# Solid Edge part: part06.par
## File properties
Author: Robert a Rhodes jr
Template: normal.par
Last saved by: Rajat Kamboj
Revision: 13
Application: Solid Edge
Accuracy: 0.99
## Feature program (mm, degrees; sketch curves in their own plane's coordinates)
sketch for "unnamed Protrusion 1" plane through (0, 0, 0) normal (0, -1, 0) x-axis (1, 0, 0)
  arc centre (60, 0) radius 30 from (60, 30) to (60, -30) cw
  line (104, -30) -> (60, -30)
  line (104, 18) -> (104, -30)
  line (164, 18) -> (104, 18)
  line (164, -4) -> (164, 18)
  line (182, -4) -> (164, -4)
  line (182, -4) -> (182, 36)
  line (142, 36) -> (182, 36)
  line (142, 30) -> (142, 36)
  line (60, 30) -> (142, 30)
extrude "unnamed Protrusion 1" add finite 54 symmetric
sketch for "ExtrudedProtrusion_6" #1 plane through (0, 0, 0) normal (0, -1, 0) x-axis (1, 0, 0)
  arc centre (60, 0) radius 30 from (60, 30) to (60, -30) ccw
  arc centre (60, 0) radius 30 from (60, 30) to (60, -30) cw
sketch for "ExtrudedProtrusion_6" #2 plane through (0, 0, 0) normal (0, -1, 0) x-axis (1, 0, 0)
  circle centre (60, 0) radius 18
extrude "ExtrudedProtrusion_6" add finite 66 symmetric
sketch for "ExtrudedProtrusion_7" plane through (0, 0, 0) normal (0, -1, 0) x-axis (1, 0, 0)
  line (104, -30) -> (164, -4)
  line (164, -4) -> (164, 18)
  line (164, 18) -> (104, 18)
  line (104, 18) -> (104, -30)
extrude "ExtrudedProtrusion_7" add finite 18 symmetric
sketch for "ExtrudedProtrusion_8" plane through (0, 0, 0) normal (0, -1, 0) x-axis (1, 0, 0)
  line (200, 76) -> (200, -4)
  line (200, -4) -> (182, -4)
  line (182, -4) -> (182, 36)
  line (182, 76) -> (182, 36)
  line (182, 76) -> (200, 76)
extrude "ExtrudedProtrusion_8" add finite 92 symmetric
sketch for "ExtrudedProtrusion_9" plane through (0, 0, 0) normal (0, -1, 0) x-axis (1, 0, 0)
  line (142, 36) -> (182, 76)
  line (182, 76) -> (182, 36)
  line (142, 36) -> (182, 36)
extrude "ExtrudedProtrusion_9" add finite 12 symmetric
sketch for "unnamed Hole 1" plane through (200, 0, 36) normal (1, 0, 0) x-axis (0, 1, 0)
hole "unnamed Hole 1" through
sketch for "Hole_1" plane through (200, 0, 36) normal (1, 0, 0) x-axis (0, 1, 0)
hole "Hole_1" diameter 16 through
pattern "unnamed Pattern 1" of "unnamed Hole 1", "Hole_1"
fillet "unnamed Round 1"
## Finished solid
Body 1: solid body, 34 faces, 81 edges, 46 vertices.
  Faces by surface: plane 28, cylinder 6
  Edges by curve: line 67, circle 14
Bounding box of the edges (mm): 170.000 x 92.000 x 106.000, from (30, -46, -30) to (200, 46, 76).
Cylindrical faces by radius (mm): R8 x2, R16 x2, R18 x1, R30 x1
Planar faces by outward normal: +x 3, +y 5, +z 4, -x 5, -y 5, -z 4, oblique 2
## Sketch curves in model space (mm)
circle centre (60, 0, 0) radius 18
line (182, 0, -4) -> (164, 0, -4)
line (104, 0, -30) -> (60, 0, -30)
arc centre (60, 0, 0) radius 30 from (60, 0, 30) through (30.0132, 0, -0.889) to (60, 0, -30)
arc centre (60, 0, 0) radius 30 from (60, 0, 30) through (89.9868, 0, -0.889) to (60, 0, -30)
line (142, 0, 36) -> (182, 0, 76)
line (142, 0, 36) -> (182, 0, 36)
line (104, 0, -30) -> (164, 0, -4)
line (182, 0, 76) -> (182, 0, 36)
line (182, 0, -4) -> (182, 0, 36)
line (142, 0, 30) -> (142, 0, 36)
line (60, 0, 30) -> (142, 0, 30)
line (104, 0, 18) -> (104, 0, -30)
line (164, 0, 18) -> (104, 0, 18)
line (164, 0, -4) -> (164, 0, 18)
line (200, 0, -4) -> (182, 0, -4)
line (200, 0, 76) -> (200, 0, -4)
line (182, 0, 76) -> (200, 0, 76)
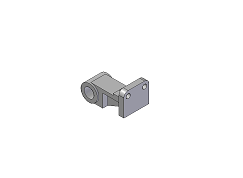
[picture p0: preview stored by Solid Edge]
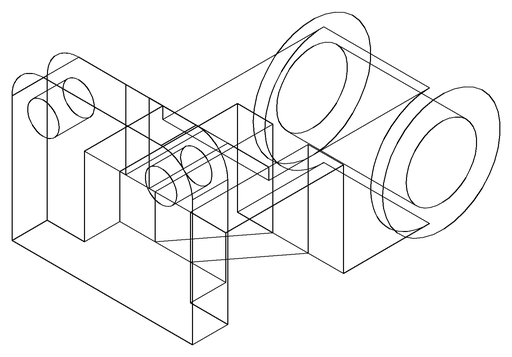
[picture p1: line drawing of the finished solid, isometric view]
